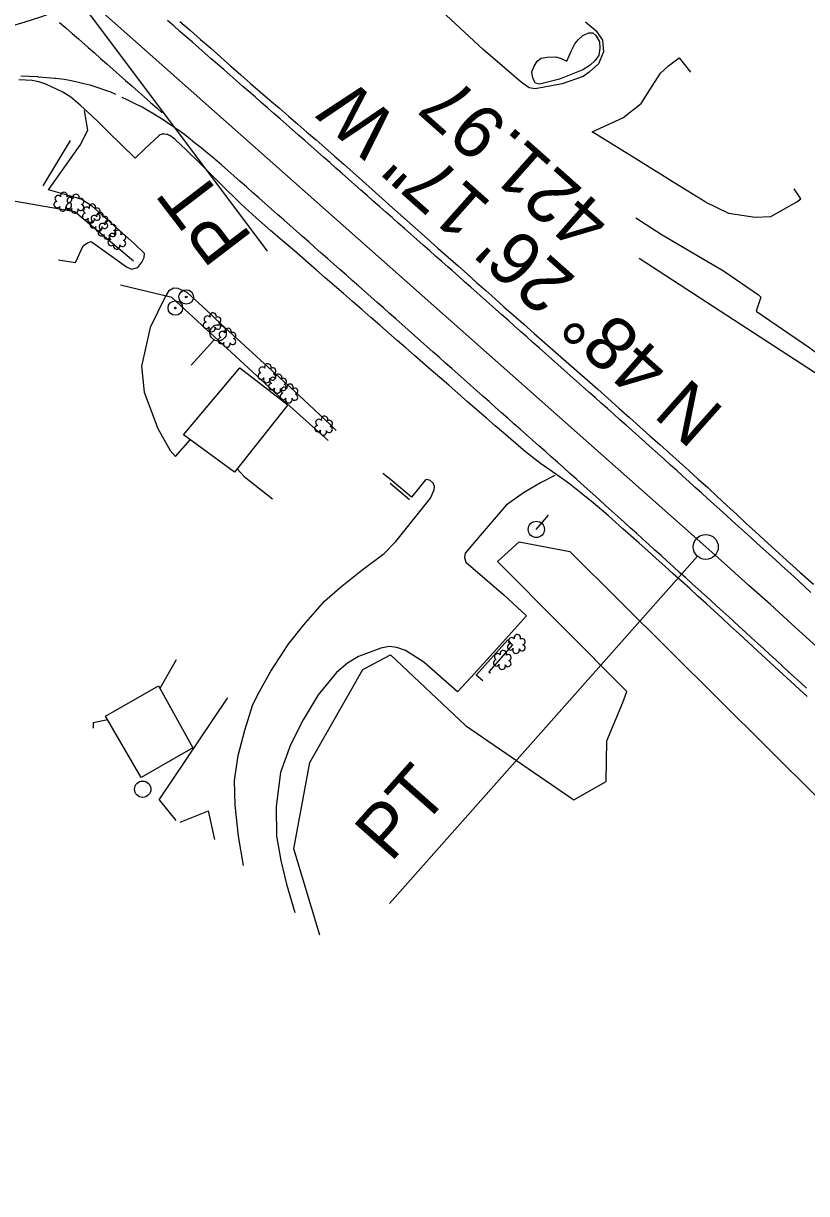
# Model space of a CAD drawing. Extents: x 474972 to 479313, y 498315 to 502691.
# Drawn here: x 476854.3 to 477089.8, y 500160.7 to 500512.6 of the extents above; entities that cross this region are included whole.
import ezdxf

# ---------------------------------------------------------------- set-up
doc = ezdxf.new("R2010")
doc.units = 0
for name, color, linetype in [('Exist Building Metal Canopy', 7, 'Continuous'), ('Exist Horizontal Alignment', 7, 'Continuous'), ('Exist Horizontal Alignment Direction Label', 7, 'Continuous'), ('Exist Other Culture Area Outline', 7, 'Continuous'), ('Exist Other Culture Fence Line', 7, 'Continuous'), ('Exist Other Culture Gate', 7, 'Continuous'), ('Exist Other Culture Sign', 7, 'Continuous'), ('Exist Roads EOP', 7, 'Continuous'), ('Exist Roads EOT', 7, 'Continuous'), ('Exist Roads Soil', 7, 'Continuous'), ('Exist Utilities Other Located Object CELL', 7, 'Continuous'), ('Exist Utilities Other Pole CELL', 7, 'Continuous'), ('Exist Utilities Power Pole CELL', 7, 'Continuous'), ('Exist Vegetation Shrub CELL', 7, 'Continuous'), ('Exist Vegetation Woods Line', 7, 'Continuous')]:
    doc.layers.add(name, color=color, linetype=linetype)

msp = doc.modelspace()

# ---------------------------------------------------------------- linework, layer by layer
at = {"layer": 'Exist Building Metal Canopy'}
for points in [[(476933.83, 500397.87), (476917.77, 500377.63), (476902.42, 500388.87), (476919.38, 500409.07), (476933.83, 500397.87)], [(476894.88, 500313.37), (476905.29, 500294.71), (476889.72, 500285.8), (476879.03, 500304.3), (476894.88, 500313.37)]]:
    msp.add_lwpolyline(points, dxfattribs=at)
at = {"layer": 'Exist Horizontal Alignment'}
for p, q in [((477059.47, 500355.18), (476743.74, 500635.12)), ((476873.56, 500516.26), (476927.6, 500444.13)), ((477056.99, 500352.37), (476964.37, 500247.91))]:
    msp.add_line(p, q, dxfattribs=at)
msp.add_circle((477059.47, 500355.18), 3.75, dxfattribs=at)
for centre, radius, start, end in [((476791.99, 500711.88), 208.48, 249.4634, 293.0343), ((475159.06, 498211.82), 2864.54, 37.33366, 48.4381)]:
    msp.add_arc(centre, radius, start, end, dxfattribs=at)
at = {"layer": 'Exist Other Culture Area Outline'}
for p, q in [((476868.31, 500477.37), (476860.13, 500463.78)), ((476964.54, 500374.35), (476970.38, 500369.43))]:
    msp.add_line(p, q, dxfattribs=at)
for points in [[(477022.5, 500509), (477024.31, 500509.8), (477025.53, 500509.82), (477026.38, 500509.04), (477027.5, 500507.09), (477027.66, 500505.15), (477027.27, 500503.11), (477026.2, 500501.47), (477024.69, 500500.1), (477022.54, 500498.62), (477015.45, 500495.85), (477009.49, 500494.38), (477008.28, 500494.65), (477007.49, 500496.13), (477007.16, 500498.02), (477007.82, 500499.79), (477008.78, 500501.27), (477009.98, 500502.13), (477011.77, 500502.49), (477014.34, 500502.55), (477016, 500502.07), (477017.73, 500501.25), (477019.11, 500504.5), (477020.14, 500506.45), (477021.1, 500507.69), (477022.5, 500509)], [(476992.46, 500314.9), (476990.48, 500316.63), (476999.93, 500327.25), (477001.37, 500325.78), (476994.22, 500317.66), (476994.7, 500317.24)]]:
    msp.add_lwpolyline(points, dxfattribs=at)
at = {"layer": 'Exist Other Culture Fence Line'}
msp.add_line((476911.9, 500267.18), (476909.93, 500275.83), dxfattribs=at)
for points in [[(476887.37, 500441.11), (476869.81, 500455.93), (476834.58, 500462.09), (476833.64, 500448.41), (476836.6, 500447.84)], [(477039.4, 500442.07), (477096.14, 500405.12), (477127.29, 500368.44), (477206.77, 500287.2), (477263.29, 500228.94), (477335.66, 500260.31)], [(476945.98, 500387.19), (476933.55, 500398.3), (476898.9, 500430.18)], [(476895.13, 500279.11), (476915.51, 500309.44), (476915.79, 500309.84)]]:
    msp.add_lwpolyline(points, dxfattribs=at)
at = {"layer": 'Exist Other Culture Gate'}
for p, q in [((476898.9, 500430.18), (476883.45, 500433.88)), ((476895.13, 500279.11), (476900.17, 500272.88)), ((476901.43, 500272.4), (476909.93, 500275.83))]:
    msp.add_line(p, q, dxfattribs=at)
at = {"layer": 'Exist Other Culture Sign'}
msp.add_line((476911.43, 500417.24), (476904.78, 500409.85), dxfattribs=at)
at = {"layer": 'Exist Roads EOP'}
for points in [[(476901.38, 500513.16), (476904.5, 500510.49), (476907.59, 500507.81), (476910.65, 500505.14), (476913.68, 500502.46), (476916.68, 500499.8), (476919.65, 500497.18), (476922.6, 500494.6), (476925.52, 500492.06), (476928.41, 500489.56), (476931.25, 500487.1), (476934.05, 500484.69), (476936.8, 500482.32), (476939.53, 500479.96), (476942.28, 500477.58), (476945.04, 500475.18), (476947.81, 500472.75), (476950.6, 500470.29), (476953.42, 500467.79), (476956.27, 500465.24), (476959.16, 500462.65), (476962.14, 500459.96), (476965.31, 500457.14), (476968.64, 500454.17), (476972.15, 500451.07), (476975.65, 500447.98), (476978.95, 500445.06), (476982.06, 500442.3), (476984.98, 500439.71), (476987.78, 500437.22), (476990.55, 500434.75), (476993.3, 500432.31), (476996.02, 500429.89), (476998.79, 500427.43), (477001.69, 500424.87), (477004.73, 500422.19), (477007.89, 500419.4), (477011.11, 500416.57), (477014.32, 500413.76), (477017.5, 500410.97), (477020.65, 500408.19), (477023.81, 500405.41), (477026.98, 500402.61), (477030.16, 500399.79), (477033.36, 500396.94), (477036.53, 500394.1), (477039.64, 500391.33), (477042.68, 500388.62), (477045.66, 500385.97), (477048.6, 500383.36), (477051.5, 500380.76), (477054.37, 500378.18), (477057.2, 500375.61), (477060.04, 500373.02), (477062.92, 500370.37), (477065.83, 500367.68), (477068.78, 500364.93), (477071.66, 500362.24), (477074.38, 500359.72), (477076.92, 500357.37), (477079.31, 500355.2), (477083.72, 500351.21), (477087.76, 500347.57), (477091.81, 500344.01)], [(477089.96, 500310.17), (477087.53, 500312.41), (477085.09, 500314.66), (477082.65, 500316.91), (477080.17, 500319.2), (477077.61, 500321.56), (477074.98, 500323.98), (477072.27, 500326.48), (477069.57, 500328.97), (477066.95, 500331.39), (477064.41, 500333.72), (477061.96, 500335.98), (477059.54, 500338.2), (477057.1, 500340.42), (477054.64, 500342.64), (477052.17, 500344.87), (477049.67, 500347.12), (477047.14, 500349.39), (477044.59, 500351.69), (477042.01, 500354.02), (477039.45, 500356.32), (477036.97, 500358.53), (477034.56, 500360.67), (477030.1, 500364.6), (477025.57, 500368.49), (477022.05, 500371.37), (477018.48, 500374.11), (477014.69, 500376.86), (477009.77, 500380.28), (477005.25, 500383.82), (477000.88, 500387.55), (476998.65, 500389.47), (476996.15, 500391.63), (476993.53, 500393.91), (476990.76, 500396.31), (476987.86, 500398.84), (476984.96, 500401.38), (476982.17, 500403.81), (476979.49, 500406.14), (476976.93, 500408.37), (476974.42, 500410.56), (476971.88, 500412.77), (476969.31, 500415.01), (476966.72, 500417.27), (476964.1, 500419.56), (476961.44, 500421.88), (476958.75, 500424.22), (476956.03, 500426.58), (476953.28, 500428.96), (476950.54, 500431.35), (476947.8, 500433.75), (476945.06, 500436.15), (476942.42, 500438.46), (476940, 500440.56), (476935.79, 500444.19), (476932.1, 500447.34), (476928.61, 500450.33), (476924.14, 500454.25), (476919.81, 500458.27), (476917.93, 500460.07), (476915.18, 500462.78), (476911.48, 500466.44), (476907.43, 500470.47), (476903.38, 500474.5), (476899.82, 500477.84), (476898.28, 500478.87), (476897.93, 500479.04), (476897.61, 500479.18), (476897.3, 500479.26), (476896.73, 500479.36), (476896.46, 500479.37), (476896.21, 500479.36), (476895.96, 500479.32), (476895.7, 500479.24), (476895.43, 500479.11), (476895.15, 500478.94), (476890.84, 500474.95), (476887.87, 500472.11), (476883.69, 500476.19), (476879.9, 500479.93), (476876.56, 500483.22), (476873.69, 500485.97), (476871.41, 500488.08), (476868.57, 500490.4), (476866.15, 500491.91), (476861, 500494.39), (476858.94, 500495.04), (476856.92, 500495.45), (476852.97, 500495.63)]]:
    msp.add_lwpolyline(points, dxfattribs=at)
at = {"layer": 'Exist Roads EOT'}
for points in [[(476865.19, 500512.94), (476867.07, 500511.29), (476868.95, 500509.64), (476870.83, 500507.99), (476871.9, 500507.05), (476873.77, 500505.39), (476875.65, 500503.74), (476877.52, 500502.08), (476879.39, 500500.43), (476881.26, 500498.77), (476883.14, 500497.12), (476885.01, 500495.46), (476886.88, 500493.81), (476888.76, 500492.16), (476890.63, 500490.5), (476892.5, 500488.85), (476894.38, 500487.19), (476896, 500485.76)], [(477091.08, 500341.49), (477089.25, 500343.2), (477087.42, 500344.91), (477085.96, 500346.27), (477084.11, 500347.94), (477082.25, 500349.62), (477080.4, 500351.3), (477078.54, 500352.97), (477076.69, 500354.65), (477074.84, 500356.33), (477072.98, 500358.01), (477071.13, 500359.68), (477069.27, 500361.36), (477067.42, 500363.04), (477065.57, 500364.71), (477063.71, 500366.39), (477061.86, 500368.07), (477060, 500369.74), (477058.15, 500371.42), (477056.3, 500373.1), (477054.44, 500374.77), (477052.59, 500376.45), (477050.73, 500378.13), (477048.88, 500379.8), (477047.03, 500381.48), (477045.17, 500383.16), (477043.32, 500384.83), (477041.47, 500386.51), (477041.13, 500386.81), (477039.26, 500388.47), (477037.4, 500390.13), (477035.53, 500391.79), (477033.66, 500393.45), (477031.79, 500395.11), (477029.92, 500396.77), (477028.05, 500398.43), (477026.19, 500400.09), (477024.32, 500401.75), (477022.45, 500403.41), (477020.58, 500405.07), (477018.71, 500406.73), (477016.84, 500408.39), (477014.98, 500410.05), (477013.11, 500411.71), (477011.24, 500413.37), (477009.37, 500415.03), (477007.5, 500416.69), (477005.63, 500418.35), (477003.77, 500420.01), (477001.9, 500421.67), (477000.03, 500423.33), (476998.16, 500424.99), (476996.29, 500426.65), (476994.42, 500428.31), (476992.55, 500429.97), (476990.69, 500431.63), (476988.82, 500433.29), (476986.95, 500434.95), (476985.08, 500436.61), (476983.21, 500438.27), (476981.99, 500439.36), (476980.12, 500441.01), (476978.24, 500442.66), (476976.37, 500444.32), (476974.5, 500445.97), (476972.62, 500447.62), (476970.75, 500449.27), (476968.87, 500450.93), (476967, 500452.58), (476965.13, 500454.23), (476963.25, 500455.89), (476961.38, 500457.54), (476959.51, 500459.19), (476957.63, 500460.85), (476955.76, 500462.5), (476953.88, 500464.15), (476952.01, 500465.81), (476950.14, 500467.46), (476948.26, 500469.11), (476946.39, 500470.77), (476944.51, 500472.42), (476942.64, 500474.07), (476940.77, 500475.72), (476938.89, 500477.38), (476937.02, 500479.03), (476935.15, 500480.68), (476933.27, 500482.34), (476931.47, 500483.93), (476929.59, 500485.57), (476927.7, 500487.22), (476925.82, 500488.86), (476923.94, 500490.51), (476922.06, 500492.15), (476920.18, 500493.8), (476918.3, 500495.44), (476916.42, 500497.09), (476914.53, 500498.73), (476912.65, 500500.38), (476910.77, 500502.02), (476908.89, 500503.66), (476907.01, 500505.31), (476905.13, 500506.95), (476903.25, 500508.6), (476901.36, 500510.24), (476899.48, 500511.89), (476897.6, 500513.53)], [(476853.54, 500496.9), (476856.03, 500496.76), (476858.53, 500496.62), (476858.81, 500496.61), (476861.3, 500496.4), (476863.79, 500496.2), (476864.06, 500496.18), (476866.54, 500495.84), (476867.65, 500495.69), (476870.08, 500495.12), (476872.51, 500494.55), (476874.3, 500494.13), (476876.67, 500493.33), (476879.03, 500492.53), (476880.47, 500492.05), (476881.97, 500491.31)], [(477089.8, 500312.68), (477087.95, 500314.37), (477086.11, 500316.06), (477084.27, 500317.75), (477082.43, 500319.44), (477080.59, 500321.13), (477078.75, 500322.82), (477076.91, 500324.51), (477075.06, 500326.2), (477073.22, 500327.89), (477071.38, 500329.58), (477069.54, 500331.27), (477067.7, 500332.96), (477066.43, 500334.12), (477064.58, 500335.8), (477062.73, 500337.48), (477060.87, 500339.15), (477059.02, 500340.83), (477057.16, 500342.51), (477055.31, 500344.18), (477053.46, 500345.86), (477051.6, 500347.54), (477049.75, 500349.21), (477047.89, 500350.89), (477046.04, 500352.57), (477044.18, 500354.25), (477042.33, 500355.92), (477040.48, 500357.6), (477038.62, 500359.28), (477036.77, 500360.95), (477034.91, 500362.63), (477033.06, 500364.31), (477031.21, 500365.98), (477029.35, 500367.66), (477027.5, 500369.34), (477025.64, 500371.01), (477023.79, 500372.69), (477021.94, 500374.37), (477020.51, 500375.66), (477018.64, 500377.31), (477016.77, 500378.97), (477014.9, 500380.63), (477013.03, 500382.29), (477011.16, 500383.95), (477009.28, 500385.61), (477007.41, 500387.26), (477005.54, 500388.92), (477003.67, 500390.58), (477001.8, 500392.24), (476999.93, 500393.9), (476998.06, 500395.55), (476996.19, 500397.21), (476994.32, 500398.87), (476992.45, 500400.53), (476990.58, 500402.19), (476988.71, 500403.84), (476986.84, 500405.5), (476984.97, 500407.16), (476983.1, 500408.82), (476981.23, 500410.48), (476979.36, 500412.14), (476977.49, 500413.79), (476975.62, 500415.45), (476973.75, 500417.11), (476971.88, 500418.77), (476970.01, 500420.43), (476968.14, 500422.08), (476966.27, 500423.74), (476964.4, 500425.4), (476962.53, 500427.06), (476960.68, 500428.7), (476958.81, 500430.35), (476956.93, 500432.01), (476955.06, 500433.66), (476953.19, 500435.31), (476951.31, 500436.97), (476949.44, 500438.62), (476947.57, 500440.28), (476945.69, 500441.93), (476943.82, 500443.58), (476941.95, 500445.24), (476940.08, 500446.89), (476938.2, 500448.55), (476936.33, 500450.2), (476934.46, 500451.85), (476932.58, 500453.51), (476930.71, 500455.16), (476928.84, 500456.82), (476926.96, 500458.47), (476925.09, 500460.13), (476923.22, 500461.78), (476921.35, 500463.43), (476919.47, 500465.09), (476917.6, 500466.74), (476915.73, 500468.4), (476913.85, 500470.05), (476911.98, 500471.7), (476911.61, 500472.03), (476909.66, 500473.6), (476907.72, 500475.17), (476905.77, 500476.74), (476903.83, 500478.31), (476902.77, 500479.17), (476900.71, 500480.59), (476898.66, 500482.02), (476896.61, 500483.44), (476895.83, 500483.98), (476893.68, 500485.25), (476891.52, 500486.51), (476889.96, 500487.43), (476887.71, 500488.53), (476885.46, 500489.62), (476884.04, 500490.31)]]:
    msp.add_lwpolyline(points, dxfattribs=at)
at = {"layer": 'Exist Roads Soil'}
for points in [[(477023.27, 500513.12), (477026.47, 500510.38), (477028.42, 500507.6), (477028.7, 500504.11), (477027.19, 500500.45), (477024.39, 500497.97), (477022.64, 500496.69), (477016.26, 500494.49), (477008.16, 500492.93), (477006.35, 500493.26), (477004.01, 500494.95), (476992.54, 500504.83), (476977.24, 500519.05)], [(477059.27, 500458.96), (477050.21, 500464.56), (477038.39, 500471.94), (477025.31, 500479.99), (477034.48, 500484.19), (477040.01, 500488.54), (477043.32, 500493.8), (477045.89, 500497.62), (477048.24, 500499.88), (477051.45, 500502.23), (477054.89, 500498)], [(476864.9, 500441.54), (476869.96, 500440.77), (476872.25, 500445.69), (476873.53, 500446.66), (476874.69, 500447), (476885.33, 500439.39), (476886.8, 500438.73), (476888.7, 500439.26), (476889.88, 500440.82), (476890.59, 500442.21), (476890.74, 500443.41), (476887.56, 500446.45), (476875.04, 500457.56), (476871.65, 500459.76), (476861.81, 500462.55), (476868.67, 500472.17), (476871.4, 500475.99), (476873.68, 500480.5), (476872.69, 500486.42)], [(477059.27, 500458.96), (477066.32, 500455.52), (477074.35, 500454.32), (477079.02, 500454.53), (477086.82, 500458.96), (477088.02, 500459.89), (477086.06, 500462.92)], [(477038.48, 500454.18), (477046.32, 500449.07)], [(477046.32, 500449.07), (477064.82, 500438.21), (477075.33, 500431.01), (477076.07, 500430.25), (477074.62, 500426.1), (477090.76, 500415.03), (477101.57, 500406.99), (477112.96, 500399.49), (477120.72, 500396.37), (477127.72, 500394.63), (477133.74, 500394.09), (477139.45, 500394.51), (477145.36, 500396.05), (477153.24, 500398.8), (477162.88, 500403.53), (477175.61, 500411.77), (477190.97, 500421.55), (477204.38, 500430.54), (477206.17, 500431.76)], [(476948.35, 500390.23), (476946.61, 500391.91), (476937, 500400.96), (476925.56, 500411.35), (476913.77, 500422.15), (476909.25, 500426.53), (476903.5, 500431.66), (476900.83, 500432.93), (476899.45, 500432.97), (476897.97, 500432.08), (476896.95, 500430.43), (476892.44, 500421.14), (476889.76, 500409.51), (476890.61, 500401.74), (476894.67, 500390.81), (476898.39, 500384.18), (476900.01, 500382.36), (476904.4, 500387.41)], [(476918.56, 500378.63), (476920.67, 500376.4), (476929.23, 500369.65)], [(476920.45, 500259.37), (476918.94, 500268.16), (476917.97, 500277.48), (476917.78, 500284.89), (476918.83, 500292.41), (476920.86, 500300.06), (476923.2, 500307.5), (476924.82, 500310.76), (476928.66, 500317.86), (476933.89, 500325.79), (476938.59, 500331.75), (476944.83, 500338.87), (476949.53, 500342.96), (476956.05, 500348.24), (476962.81, 500353.19), (476966.25, 500356.77), (476971.84, 500363.79), (476976.68, 500369.83), (476977.84, 500372.32), (476977.9, 500373.35), (476977.5, 500374.31), (476976.64, 500375.14), (476975.69, 500375.49), (476975.22, 500375.39), (476971.02, 500370.12), (476965.17, 500375.07), (476962.37, 500377.28)], [(477014.06, 500376.67), (477009.75, 500374.44), (477004.63, 500371.49), (476999.5, 500367.71), (476991.6, 500358.57), (476987.14, 500353.33), (476986.94, 500352.01), (476987.31, 500350.57), (476998.73, 500340.75), (477005.54, 500334.43), (476997.41, 500325.47), (476988.85, 500315.9), (476984.79, 500311.64), (476974.73, 500320.49), (476969.2, 500324.01), (476966.54, 500324.9), (476964.32, 500325.19), (476961.78, 500324.7), (476955.02, 500322.18), (476951.77, 500320.23), (476948.42, 500317.38), (476942.89, 500310.68), (476938.39, 500303.19), (476934.6, 500295.69), (476931.59, 500287.38), (476930.25, 500277.08), (476930.44, 500268.15), (476931.65, 500260.85), (476933.37, 500253.78), (476935.92, 500245.23)], [(476900.19, 500321.18), (476895.35, 500312.57), (476895.38, 500312.47)], [(476879.69, 500303.16), (476875.25, 500302.27), (476875.28, 500300.64)]]:
    msp.add_lwpolyline(points, dxfattribs=at)
at = {"layer": 'Exist Utilities Other Located Object CELL'}
for centre, radius in [((476903.25, 500430.36), 2.18), ((476899.98, 500427.02), 2.18), ((476903.25, 500430.36), 0.24), ((476899.98, 500427.02), 0.24)]:
    msp.add_circle(centre, radius, dxfattribs=at)
at = {"layer": 'Exist Utilities Other Pole CELL'}
for centre in [(476912.85, 500419.56), (476890.18, 500282.32)]:
    msp.add_circle(centre, 2.46, dxfattribs=at)
at = {"layer": 'Exist Utilities Power Pole CELL'}
for q in [(477012.14, 500364.76), (477008.52, 500360.45)]:
    msp.add_line((477008.52, 500360.45), q, dxfattribs=at)
msp.add_circle((477008.52, 500360.45), 2.45, dxfattribs=at)
at = {"layer": 'Exist Vegetation Shrub CELL'}
for p, q in [((476866.23, 500458.83), (476866.23, 500458.83)), ((476869.88, 500458.21), (476869.88, 500458.21)), ((476874.8, 500455.3), (476874.8, 500455.3)), ((476877.07, 500452.77), (476877.07, 500452.77)), ((476879.54, 500450.39), (476879.54, 500450.39)), ((476882.47, 500447.4), (476882.47, 500447.4)), ((476911.1, 500422.56), (476911.1, 500422.56)), ((476915.59, 500417.92), (476915.59, 500417.92)), ((476927.59, 500407.23), (476927.59, 500407.23)), ((476930.78, 500404.11), (476930.78, 500404.11)), ((476934.23, 500401.13), (476934.23, 500401.13)), ((476944.61, 500391.47), (476944.61, 500391.47)), ((477002.59, 500325.81), (477002.59, 500325.81)), ((476998.36, 500321.01), (476998.36, 500321.01))]:
    msp.add_line(p, q, dxfattribs=at)
for centre, radius, start, end in [((476864.75, 500459.95), 0.968, 35.8908, 245.4216), ((476866.46, 500460.87), 0.99, 334.8391, 200.4717), ((476867.9, 500459.7), 0.929, 284.4567, 126.0861), ((476868.4, 500459.33), 0.968, 35.8908, 245.4216), ((476870.11, 500460.25), 0.99, 334.8391, 200.4717), ((476871.55, 500459.08), 0.929, 284.4567, 126.0861), ((476864.43, 500458.12), 0.955, 95.1099, 327.9534), ((476866.1, 500457.14), 0.984, 151.2797, 21.387), ((476867.87, 500457.9), 0.937, 204.9913, 73.4601), ((476868.08, 500457.5), 0.955, 95.1099, 327.9534), ((476869.75, 500456.52), 0.984, 151.2797, 21.387), ((476871.52, 500457.28), 0.937, 204.9913, 73.4601), ((476873.32, 500456.43), 0.968, 35.8908, 245.4216), ((476875.03, 500457.34), 0.99, 334.8391, 200.4717), ((476876.47, 500456.17), 0.929, 284.4567, 126.0861), ((476877.3, 500454.81), 0.99, 334.8391, 200.4717), ((476873, 500454.6), 0.955, 95.1099, 327.9534), ((476874.67, 500453.62), 0.984, 151.2797, 21.387), ((476875.27, 500452.06), 0.955, 95.1099, 327.9534), ((476875.59, 500453.9), 0.968, 35.8908, 245.4216), ((476876.44, 500454.37), 0.937, 204.9913, 73.4601), ((476878.06, 500451.52), 0.968, 35.8908, 245.4216), ((476878.71, 500451.84), 0.937, 204.9913, 73.4601), ((476878.75, 500453.64), 0.929, 284.4567, 126.0861), ((476879.77, 500452.43), 0.99, 334.8391, 200.4717), ((476881.21, 500451.26), 0.929, 284.4567, 126.0861), ((476876.95, 500451.09), 0.984, 151.2797, 21.387), ((476877.74, 500449.69), 0.955, 95.1099, 327.9534), ((476879.41, 500448.71), 0.984, 151.2797, 21.387), ((476880.99, 500448.52), 0.968, 35.8908, 245.4216), ((476881.18, 500449.47), 0.937, 204.9913, 73.4601), ((476882.7, 500449.44), 0.99, 334.8391, 200.4717), ((476884.14, 500448.27), 0.929, 284.4567, 126.0861), ((476880.67, 500446.69), 0.955, 95.1099, 327.9534), ((476882.34, 500445.71), 0.984, 151.2797, 21.387), ((476884.11, 500446.47), 0.937, 204.9913, 73.4601), ((476909.62, 500423.69), 0.968, 35.8908, 245.4216), ((476911.33, 500424.6), 0.99, 334.8391, 200.4717), ((476912.78, 500423.43), 0.929, 284.4567, 126.0861), ((476909.3, 500421.85), 0.955, 95.1099, 327.9534), ((476910.98, 500420.88), 0.984, 151.2797, 21.387), ((476912.74, 500421.63), 0.937, 204.9913, 73.4601), ((476915.82, 500419.96), 0.99, 334.8391, 200.4717), ((476913.79, 500417.22), 0.955, 95.1099, 327.9534), ((476914.1, 500419.05), 0.968, 35.8908, 245.4216), ((476917.22, 500416.99), 0.937, 204.9913, 73.4601), ((476917.26, 500418.79), 0.929, 284.4567, 126.0861), ((476915.46, 500416.24), 0.984, 151.2797, 21.387), ((476927.81, 500409.27), 0.99, 334.8391, 200.4717), ((476925.79, 500406.53), 0.955, 95.1099, 327.9534), ((476926.1, 500408.36), 0.968, 35.8908, 245.4216), ((476929.22, 500406.3), 0.937, 204.9913, 73.4601), ((476929.26, 500408.1), 0.929, 284.4567, 126.0861), ((476931.01, 500406.15), 0.99, 334.8391, 200.4717), ((476927.46, 500405.55), 0.984, 151.2797, 21.387), ((476928.98, 500403.4), 0.955, 95.1099, 327.9534), ((476929.3, 500405.23), 0.968, 35.8908, 245.4216), ((476930.66, 500402.42), 0.984, 151.2797, 21.387), ((476932.42, 500403.18), 0.937, 204.9913, 73.4601), ((476932.75, 500402.26), 0.968, 35.8908, 245.4216), ((476932.46, 500404.98), 0.929, 284.4567, 126.0861), ((476934.46, 500403.17), 0.99, 334.8391, 200.4717), ((476935.9, 500402), 0.929, 284.4567, 126.0861), ((476932.43, 500400.42), 0.955, 95.1099, 327.9534), ((476934.1, 500399.45), 0.984, 151.2797, 21.387), ((476935.86, 500400.2), 0.937, 204.9913, 73.4601), ((476943.13, 500392.6), 0.968, 35.8908, 245.4216), ((476944.84, 500393.51), 0.99, 334.8391, 200.4717), ((476946.29, 500392.34), 0.929, 284.4567, 126.0861), ((476942.81, 500390.76), 0.955, 95.1099, 327.9534), ((476944.48, 500389.79), 0.984, 151.2797, 21.387), ((476946.25, 500390.54), 0.937, 204.9913, 73.4601), ((477000.79, 500325.1), 0.955, 95.1099, 327.9534), ((477001.11, 500326.94), 0.968, 35.8908, 245.4216), ((477002.82, 500327.85), 0.99, 334.8391, 200.4717), ((477004.23, 500324.88), 0.937, 204.9913, 73.4601), ((477004.26, 500326.68), 0.929, 284.4567, 126.0861), ((476996.87, 500322.14), 0.968, 35.8908, 245.4216), ((476998.59, 500323.05), 0.99, 334.8391, 200.4717), ((477000.03, 500321.88), 0.929, 284.4567, 126.0861), ((477002.46, 500324.13), 0.984, 151.2797, 21.387), ((476996.56, 500320.31), 0.955, 95.1099, 327.9534), ((476998.23, 500319.33), 0.984, 151.2797, 21.387), ((476999.99, 500320.09), 0.937, 204.9913, 73.4601)]:
    msp.add_arc(centre, radius, start, end, dxfattribs=at)
at = {"layer": 'Exist Vegetation Woods Line'}
msp.add_lwpolyline([(476943.38, 500238.41), (476935.63, 500264.39), (476940.38, 500290.33), (476956.31, 500318.31), (476964.65, 500322.73), (476987.23, 500301.46), (477019.76, 500279.11), (477029.53, 500284.67), (477029.69, 500296.87), (477034.51, 500308.35), (477035.72, 500311.75), (476996.88, 500350.75), (477003.33, 500356.68), (477018.56, 500353.82), (477167.87, 500205.55)], dxfattribs=at)

# ---------------------------------------------------------------- texts
at = {"layer": 'Exist Horizontal Alignment'}
for rotation, p in [(127.3978, (476923.53, 500448.2)), (48.4381, (476964.75, 500260.02))]:
    msp.add_text('PT', height=16, rotation=rotation, dxfattribs=at).set_placement(p)
at = {"layer": 'Exist Horizontal Alignment Direction Label'}
for s, p in [('N 48%%d 26\' 17" W', (477065.53, 500396.26)), ('421.97', (477031.86, 500454.57))]:
    msp.add_text(s, height=16, rotation=138.4381, dxfattribs=at).set_placement(p)

doc.saveas('drawing.dxf')
